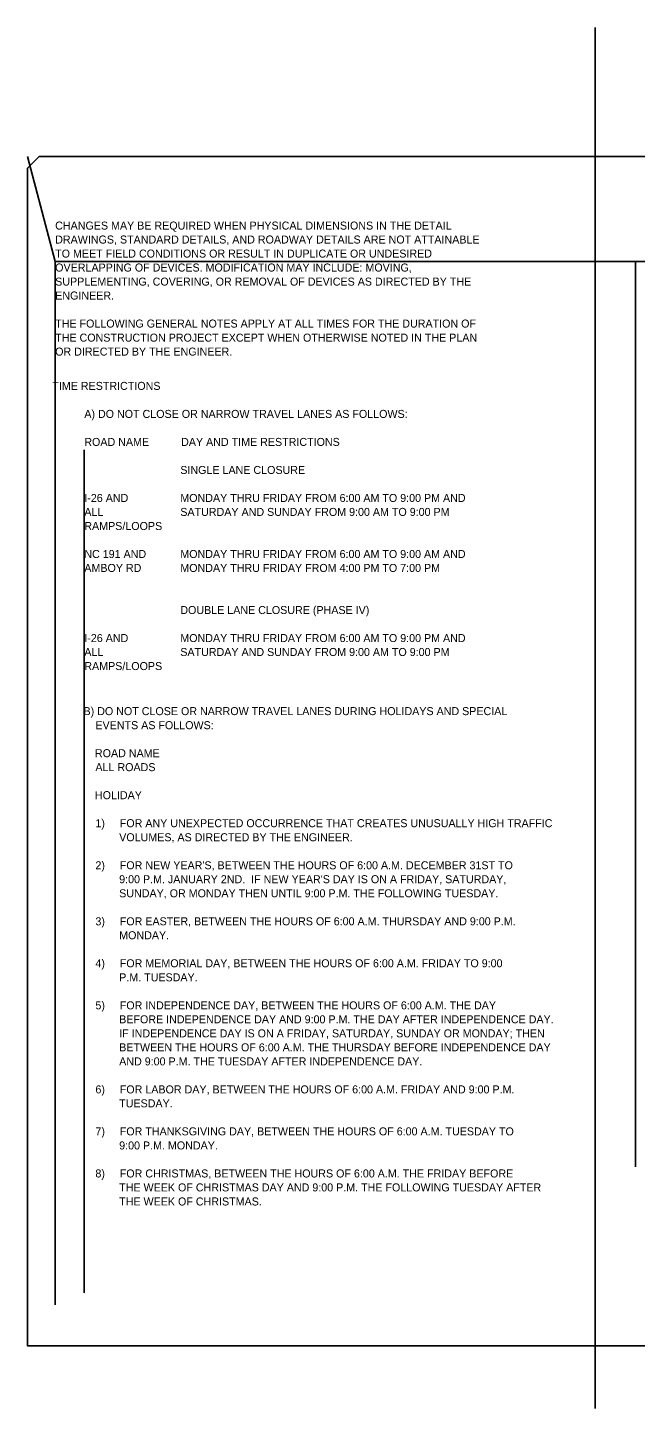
# Model space of a CAD drawing. Extents: x 2485109 to 2490507, y 368607 to 371384.
# Drawn here: x 2487017 to 2487548, y 370164 to 371371 of the extents above; entities that cross this region are included whole.
import ezdxf

# ---------------------------------------------------------------- set-up
doc = ezdxf.new("R2010")
doc.units = 0
for name, color, linetype in [('Scratch_Level_2', 7, 'Continuous'), ('Scratch_Level_3', 7, 'Continuous'), ('Scratch_Level_4', 7, 'Continuous'), ('TC SHEET LAYOUT SHAPE', 7, 'Continuous'), ('TC SHEET TEXT', 7, 'Continuous')]:
    doc.layers.add(name, color=color, linetype=linetype)

msp = doc.modelspace()

# ---------------------------------------------------------------- linework, layer by layer
at = {"layer": 'Scratch_Level_2'}
msp.add_line((2487513.2, 370163.7), (2487513.2, 371371.1), dxfattribs=at)
at = {"layer": 'Scratch_Level_3'}
msp.add_line((2487016.6, 371258.3), (2487016.6, 371258.3), dxfattribs=at)
at = {"layer": 'Scratch_Level_4'}
for p, q in [((2487016.6, 371258.3), (2487040.7, 371166.6)), ((2487040.7, 371166.6), (2488050.1, 371166.6)), ((2487040.7, 371166.6), (2487040.7, 370254.3)), ((2487548.4, 371166.6), (2487548.4, 370374.9)), ((2487066.2, 371001.9), (2487066.2, 370264.6))]:
    msp.add_line(p, q, dxfattribs=at)
at = {"layer": 'TC SHEET LAYOUT SHAPE'}
msp.add_lwpolyline([(2487016.6, 370666.8), (2487016.6, 370976.2), (2487016.6, 371248.3), (2487026.6, 371258.3), (2487469.6, 371258.3), (2487940.6, 371258.3), (2488261.6, 371258.3), (2488261.6, 371178.3), (2488346.6, 371178.3), (2488346.6, 371226.3), (2488506.6, 371226.3), (2488506.6, 370891.3), (2488506.6, 370612.1), (2488506.6, 370360.8), (2487778.4, 370360.8), (2487778.4, 370218.3), (2487608.9, 370218.3), (2487256.1, 370218.3), (2487016.6, 370218.3)], close=True, dxfattribs=at)

# ---------------------------------------------------------------- texts
at = {"layer": 'TC SHEET TEXT'}
for s, p in [('CHANGES MAY BE REQUIRED WHEN PHYSICAL DIMENSIONS IN THE DETAIL', (2487040.7, 371194.5)), ('DRAWINGS, STANDARD DETAILS, AND ROADWAY DETAILS ARE NOT ATTAINABLE', (2487040.7, 371182.3)), ('TO MEET FIELD CONDITIONS OR RESULT IN DUPLICATE OR UNDESIRED', (2487040.7, 371170)), ('OVERLAPPING OF DEVICES. MODIFICATION MAY INCLUDE: MOVING,', (2487040.7, 371157.8)), ('SUPPLEMENTING, COVERING, OR REMOVAL OF DEVICES AS DIRECTED BY THE', (2487040.7, 371145.5)), ('ENGINEER.', (2487040.7, 371133.3)), ('THE FOLLOWING GENERAL NOTES APPLY AT ALL TIMES FOR THE DURATION OF', (2487040.7, 371108.8)), ('THE CONSTRUCTION PROJECT EXCEPT WHEN OTHERWISE NOTED IN THE PLAN', (2487040.7, 371096.5)), ('OR DIRECTED BY THE ENGINEER.', (2487040.7, 371084.3)), ('TIME RESTRICTIONS', (2487038.2, 371054.3)), ('A) DO NOT CLOSE OR NARROW TRAVEL LANES AS FOLLOWS:', (2487066.2, 371029.8)), ('ROAD NAME', (2487066.2, 371005.3)), ('DAY AND TIME RESTRICTIONS', (2487150.9, 371005.3)), ('SINGLE LANE CLOSURE', (2487150.2, 370980.8)), ('I-26 AND', (2487066.2, 370956.3)), ('MONDAY THRU FRIDAY FROM 6:00 AM TO 9:00 PM AND', (2487150.2, 370956.3)), ('ALL ', (2487066.2, 370944.1)), ('SATURDAY AND SUNDAY FROM 9:00 AM TO 9:00 PM', (2487150.2, 370944.1)), ('RAMPS/LOOPS', (2487066.2, 370931.8)), ('NC 191 AND', (2487066.2, 370907.3)), ('MONDAY THRU FRIDAY FROM 6:00 AM TO 9:00 AM AND', (2487150.2, 370907.3)), ('AMBOY RD', (2487066.2, 370895.1)), ('MONDAY THRU FRIDAY FROM 4:00 PM TO 7:00 PM ', (2487150.2, 370895.1)), ('DOUBLE LANE CLOSURE (PHASE IV)', (2487150.2, 370858.3)), ('I-26 AND', (2487066.2, 370833.8)), ('MONDAY THRU FRIDAY FROM 6:00 AM TO 9:00 PM AND', (2487150.2, 370833.8)), ('ALL ', (2487066.2, 370821.6)), ('SATURDAY AND SUNDAY FROM 9:00 AM TO 9:00 PM', (2487150.2, 370821.6)), ('RAMPS/LOOPS', (2487066.2, 370809.3)), ('B) DO NOT CLOSE OR NARROW TRAVEL LANES DURING HOLIDAYS AND SPECIAL', (2487065.5, 370769.9)), ('    EVENTS AS FOLLOWS:', (2487065.5, 370757.6)), ('ROAD NAME', (2487075.5, 370733.1)), ('    ALL ROADS', (2487065.5, 370720.9)), ('HOLIDAY', (2487075.5, 370696.4)), ('    1)     FOR ANY UNEXPECTED OCCURRENCE THAT CREATES UNUSUALLY HIGH TRAFFIC', (2487065.5, 370671.9)), ('            VOLUMES, AS DIRECTED BY THE ENGINEER.', (2487065.5, 370659.6)), ("    2)     FOR NEW YEAR'S, BETWEEN THE HOURS OF 6:00 A.M. DECEMBER 31ST TO", (2487065.5, 370635.1)), ("            9:00 P.M. JANUARY 2ND.  IF NEW YEAR'S DAY IS ON A FRIDAY, SATURDAY,", (2487065.5, 370622.9)), ('            SUNDAY, OR MONDAY THEN UNTIL 9:00 P.M. THE FOLLOWING TUESDAY.', (2487065.5, 370610.6)), ('    3)     FOR EASTER, BETWEEN THE HOURS OF 6:00 A.M. THURSDAY AND 9:00 P.M.', (2487065.5, 370586.1)), ('            MONDAY.', (2487065.5, 370573.9)), ('    4)     FOR MEMORIAL DAY, BETWEEN THE HOURS OF 6:00 A.M. FRIDAY TO 9:00', (2487065.5, 370549.4)), ('            P.M. TUESDAY.', (2487065.5, 370537.1)), ('    5)     FOR INDEPENDENCE DAY, BETWEEN THE HOURS OF 6:00 A.M. THE DAY', (2487065.5, 370512.6)), ('            BEFORE INDEPENDENCE DAY AND 9:00 P.M. THE DAY AFTER INDEPENDENCE DAY.', (2487065.5, 370500.4)), ('            IF INDEPENDENCE DAY IS ON A FRIDAY, SATURDAY, SUNDAY OR MONDAY; THEN', (2487065.5, 370488.1)), ('            BETWEEN THE HOURS OF 6:00 A.M. THE THURSDAY BEFORE INDEPENDENCE DAY', (2487065.5, 370475.9)), ('            AND 9:00 P.M. THE TUESDAY AFTER INDEPENDENCE DAY.', (2487065.5, 370463.6)), ('    6)     FOR LABOR DAY, BETWEEN THE HOURS OF 6:00 A.M. FRIDAY AND 9:00 P.M.', (2487065.5, 370439.1)), ('            TUESDAY.', (2487065.5, 370426.9)), ('    7)     FOR THANKSGIVING DAY, BETWEEN THE HOURS OF 6:00 A.M. TUESDAY TO', (2487065.5, 370402.4)), ('            9:00 P.M. MONDAY.', (2487065.5, 370390.1)), ('    8)     FOR CHRISTMAS, BETWEEN THE HOURS OF 6:00 A.M. THE FRIDAY BEFORE', (2487065.5, 370365.6)), ('            THE WEEK OF CHRISTMAS DAY AND 9:00 P.M. THE FOLLOWING TUESDAY AFTER', (2487065.5, 370353.4)), ('            THE WEEK OF CHRISTMAS.', (2487065.5, 370341.1))]:
    msp.add_text(s, height=7, dxfattribs=at).set_placement(p)

doc.saveas('drawing.dxf')
